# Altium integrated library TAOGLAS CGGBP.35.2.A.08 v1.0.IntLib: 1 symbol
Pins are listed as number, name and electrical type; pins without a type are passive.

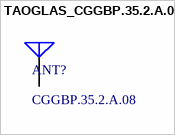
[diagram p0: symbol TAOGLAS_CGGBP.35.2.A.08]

## TAOGLAS_CGGBP.35.2.A.08
designator ANT?, comment CGGBP.35.2.A.08
GPS/GLONASS/GALILEO/BeiDou L1 Embedded Patch Antenna 35x35x2mm; ComponentLibStatus: Created; MFG: Taoglas; Temp_High: +85C; Temp_Low: -40C
footprint TAOGLAS_CGGBP.35.2.A.08 (GPS/GLONASS/GALILEO/BeiDou L1 Embedded Patch Antenna 35x35x2mm)
pins: 1 RF FEED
